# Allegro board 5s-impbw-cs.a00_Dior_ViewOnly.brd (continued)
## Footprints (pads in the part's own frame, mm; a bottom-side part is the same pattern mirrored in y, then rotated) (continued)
MX_BTOB_60P_20_F_PANA
  rect 0.762x2.007 smd: 1(-7.5,-2.2) 30(7.5,-2.2) 31(-7.5,2.2) 60(7.5,2.2)
  rect 0.254x2.007 smd: 2(-6.75,-2.2) 3(-6.25,-2.2) 4(-5.75,-2.2) 5(-5.25,-2.2) 6(-4.75,-2.2) 7(-4.25,-2.2) 8(-3.75,-2.2) 9(-3.25,-2.2) 10(-2.75,-2.2) 11(-2.25,-2.2) 12(-1.75,-2.2) 13(-1.25,-2.2) 14(-0.75,-2.2) 15(-0.25,-2.2) 16(0.25,-2.2) 17(0.75,-2.2) 18(1.25,-2.2) 19(1.75,-2.2) 20(2.25,-2.2) 21(2.75,-2.2) 22(3.25,-2.2) 23(3.75,-2.2) 24(4.25,-2.2) 25(4.75,-2.2) 26(5.25,-2.2) 27(5.75,-2.2) 28(6.25,-2.2) 29(6.75,-2.2) 32(-6.75,2.2) 33(-6.25,2.2) 34(-5.75,2.2) 35(-5.25,2.2) 36(-4.75,2.2) 37(-4.25,2.2) 38(-3.75,2.2) 39(-3.25,2.2) 40(-2.75,2.2) 41(-2.25,2.2) 42(-1.75,2.2) 43(-1.25,2.2) 44(-0.75,2.2) 45(-0.25,2.2) 46(0.25,2.2) 47(0.75,2.2) 48(1.25,2.2) 49(1.75,2.2) 50(2.25,2.2) 51(2.75,2.2) 52(3.25,2.2) 53(3.75,2.2) 54(4.25,2.2) 55(4.75,2.2) 56(5.25,2.2) 57(5.75,2.2) 58(6.25,2.2) 59(6.75,2.2)
MX_C0402
  rect 0.635x0.635 smd: 1(-0.445,0) 2(0.445,0)
MX_C0402_SMALL
  rect 0.457x0.508 smd: 1(0.419,0) 2(-0.419,0)
MX_C0603
  rect 0.889x0.813 smd: 1(-0.635,0) 2(0.635,0)
MX_C0603_SMALL
  rect 0.559x0.889 smd: 1(-0.67,0) 2(0.67,0)
MX_C0805
  rect 1.27x1.27 smd: 1(1.041,0) 2(-1.041,0)
MX_C0805_SMALL
  rect 0.813x1.397 smd: 1(0.9,0) 2(-0.9,0)
MX_C3528
  rect 1.905x2.21 smd: 1(1.816,0) 2(-1.816,0)
MX_C7343D_H75
  rect 2.032x2.616 smd: 1(3.265,0) 2(-3.265,0)
MX_C7343D_H79
  rect 2.032x2.616 smd: 1(3.265,0) 2(-3.265,0)
MX_CHOKE_4P_79X47_FUKUI
  rect 0.889x0.356 smd: 1(-0.85,-0.425) 2(0.85,-0.425) 3(0.85,0.425) 4(-0.85,0.425)
MX_DDR3_DIMM_204P_24_4HL_DA
  round 1.6 hole 1.6 unplated: (-33.4,0)
  round 1.092 hole 1.092 unplated: (33.4,0)
  rect 0.356x2.007 smd: 1(-31.65,-4.1) 2(-31.35,4.1) 3(-31.05,-4.1) 4(-30.75,4.1) 5(-30.45,-4.1) 6(-30.15,4.1) 7(-29.85,-4.1) 8(-29.55,4.1) 9(-29.25,-4.1) 10(-28.95,4.1) 11(-28.65,-4.1) 12(-28.35,4.1) 13(-28.05,-4.1) 14(-27.75,4.1) 15(-27.45,-4.1) 16(-27.15,4.1) 17(-26.85,-4.1) 18(-26.55,4.1) 19(-26.25,-4.1) 20(-25.95,4.1) 21(-25.65,-4.1) 22(-25.35,4.1) 23(-25.05,-4.1) 24(-24.75,4.1) 25(-24.45,-4.1) 26(-24.15,4.1) 27(-23.85,-4.1) 28(-23.55,4.1) 29(-23.25,-4.1) 30(-22.95,4.1) 31(-22.65,-4.1) 32(-22.35,4.1) 33(-22.05,-4.1) 34(-21.75,4.1) 35(-21.45,-4.1) 36(-21.15,4.1) 37(-20.85,-4.1) 38(-20.55,4.1) 39(-20.25,-4.1) 40(-19.95,4.1) 41(-19.65,-4.1) 42(-19.35,4.1) 43(-19.05,-4.1) 44(-18.75,4.1) 45(-18.45,-4.1) 46(-18.15,4.1) 47(-17.85,-4.1) 48(-17.55,4.1) 49(-17.25,-4.1) 50(-16.95,4.1) 51(-16.65,-4.1) 52(-16.35,4.1) 53(-16.05,-4.1) 54(-15.75,4.1) 55(-15.45,-4.1) 56(-15.15,4.1) 57(-14.85,-4.1) 58(-14.55,4.1) 59(-14.25,-4.1) 60(-13.95,4.1) 61(-13.65,-4.1) 62(-13.35,4.1) 63(-13.05,-4.1) 64(-12.75,4.1) 65(-12.45,-4.1) 66(-12.15,4.1) 67(-11.85,-4.1) 68(-11.55,4.1) 69(-11.25,-4.1) 70(-10.95,4.1) 71(-10.65,-4.1) 72(-10.35,4.1) 73(-7.65,-4.1) 74(-7.35,4.1) 75(-7.05,-4.1) 76(-6.75,4.1) 77(-6.45,-4.1) 78(-6.15,4.1) 79(-5.85,-4.1) 80(-5.55,4.1) 81(-5.25,-4.1) 82(-4.95,4.1) 83(-4.65,-4.1) 84(-4.35,4.1) 85(-4.05,-4.1) 86(-3.75,4.1) 87(-3.45,-4.1) 88(-3.15,4.1) 89(-2.85,-4.1) 90(-2.55,4.1) 91(-2.25,-4.1) 92(-1.95,4.1) 93(-1.65,-4.1) 94(-1.35,4.1) 95(-1.05,-4.1) 96(-0.75,4.1) 97(-0.45,-4.1) 98(-0.15,4.1) 99(0.15,-4.1) 100(0.45,4.1) 101(0.75,-4.1) 102(1.05,4.1) 103(1.35,-4.1) 104(1.65,4.1) 105(1.95,-4.1) 106(2.25,4.1) 107(2.55,-4.1) 108(2.85,4.1) 109(3.15,-4.1) 110(3.45,4.1) 111(3.75,-4.1) 112(4.05,4.1) 113(4.35,-4.1) 114(4.65,4.1) 115(4.95,-4.1) 116(5.25,4.1) 117(5.55,-4.1) 118(5.85,4.1) 119(6.15,-4.1) 120(6.45,4.1) 121(6.75,-4.1) 122(7.05,4.1) 123(7.35,-4.1) 124(7.65,4.1) 125(7.95,-4.1) 126(8.25,4.1) 127(8.55,-4.1) 128(8.85,4.1) 129(9.15,-4.1) 130(9.45,4.1) 131(9.75,-4.1) 132(10.05,4.1) 133(10.35,-4.1) 134(10.65,4.1) 135(10.95,-4.1) 136(11.25,4.1) 137(11.55,-4.1) 138(11.85,4.1) 139(12.15,-4.1) 140(12.45,4.1) 141(12.75,-4.1) 142(13.05,4.1) 143(13.35,-4.1) 144(13.65,4.1) 145(13.95,-4.1) 146(14.25,4.1) 147(14.55,-4.1) 148(14.85,4.1) 149(15.15,-4.1) 150(15.45,4.1) 151(15.75,-4.1) 152(16.05,4.1) 153(16.35,-4.1) 154(16.65,4.1) 155(16.95,-4.1) 156(17.25,4.1) 157(17.55,-4.1) 158(17.85,4.1) 159(18.15,-4.1) 160(18.45,4.1) 161(18.75,-4.1) 162(19.05,4.1) 163(19.35,-4.1) 164(19.65,4.1) 165(19.95,-4.1) 166(20.25,4.1) 167(20.55,-4.1) 168(20.85,4.1) 169(21.15,-4.1) 170(21.45,4.1) 171(21.75,-4.1) 172(22.05,4.1) 173(22.35,-4.1) 174(22.65,4.1) 175(22.95,-4.1) 176(23.25,4.1) 177(23.55,-4.1) 178(23.85,4.1) 179(24.15,-4.1) 180(24.45,4.1) 181(24.75,-4.1) 182(25.05,4.1) 183(25.35,-4.1) 184(25.65,4.1) 185(25.95,-4.1) 186(26.25,4.1) 187(26.55,-4.1) 188(26.85,4.1) 189(27.15,-4.1) 190(27.45,4.1) 191(27.75,-4.1) 192(28.05,4.1) 193(28.35,-4.1) 194(28.65,4.1) 195(28.95,-4.1) 196(29.25,4.1) 197(29.55,-4.1) 198(29.85,4.1) 199(30.15,-4.1) 200(30.45,4.1) 201(30.75,-4.1) 202(31.05,4.1) 203(31.35,-4.1) 204(31.65,4.1)
  rect 4.496x4.597 smd: 207(-32.55,12) 208(32.55,12)
MX_DFN_6P_26_79X79_2PAD_IR
  rect 0.381x0.457 smd: 1(-0.65,-0.925) 2(0,-0.925) 3(0.65,-0.925) 4(0.65,0.925) 5(0,0.925) 6(-0.65,0.925)
  rect 1.041x0.965 smd: 7(-0.28,0.002)
  rect 0.229x0.787 smd: 8(0.735,0.002)
MX_ESD_2P_33_39X24_AMA
  rect 0.559x0.61 smd: 1(0.425,0) 2(-0.425,0)
MX_FPC_1X12P_20_2H
  rect 0.292x1.092 smd: 1(-2.75,1.95) 2(-2.25,1.95) 3(-1.75,1.95) 4(-1.25,1.95) 5(-0.75,1.95) 6(-0.25,1.95) 7(0.25,1.95) 8(0.75,1.95) 9(1.25,1.95) 10(1.75,1.95) 11(2.25,1.95) 12(2.75,1.95)
  custom 0.6x0.6 smd: 13(-4.85,0) 14(4.85,0)
MX_FPC_7P_20_2HOLD_RA_ENT_T
  rect 0.292x0.991 smd: 1(-1.5,1.6) 2(-1,1.6) 3(-0.5,1.6) 4(0,1.6) 5(0.5,1.6) 6(1,1.6) 7(1.5,1.6)
  rect 1.499x2.591 smd: 8(-3.85,0) 9(3.85,0)
MX_FPC_10P_20_2H_RA_AC_H79
  rect 0.292x1.092 smd: 1(-2.25,1.95) 2(-1.75,1.95) 3(-1.25,1.95) 4(-0.75,1.95) 5(-0.25,1.95) 6(0.25,1.95) 7(0.75,1.95) 8(1.25,1.95) 9(1.75,1.95) 10(2.25,1.95)
  custom 0.6x0.6 smd: 11(-4.35,0) 12(4.35,0)
MX_FPC_18P_20_2HD_RA_ACE_B
  rect 0.292x1.194 smd: 1(-4.25,3.2) 2(-3.75,3.2) 3(-3.25,3.2) 4(-2.75,3.2) 5(-2.25,3.2) 6(-1.75,3.2) 7(-1.25,3.2) 8(-0.75,3.2) 9(-0.25,3.2) 10(0.25,3.2) 11(0.75,3.2) 12(1.25,3.2) 13(1.75,3.2) 14(2.25,3.2) 15(2.75,3.2) 16(3.25,3.2) 17(3.75,3.2) 18(4.25,3.2)
  rect 2.007x1.803 smd: 19(-7.15,0) 20(7.15,0)
MX_FPC_26P_20_4HD_RA_PANASO
  rect 0.292x0.787 smd: 1(-6.25,2.5) 2(-5.75,2.5) 3(-5.25,2.5) 4(-4.75,2.5) 5(-4.25,2.5) 6(-3.75,2.5) 7(-3.25,2.5) 8(-2.75,2.5) 9(-2.25,2.5) 10(-1.75,2.5) 11(-1.25,2.5) 12(-0.75,2.5) 13(-0.25,2.5) 14(0.25,2.5) 15(0.75,2.5) 16(1.25,2.5) 17(1.75,2.5) 18(2.25,2.5) 19(2.75,2.5) 20(3.25,2.5) 21(3.75,2.5) 22(4.25,2.5) 23(4.75,2.5) 24(5.25,2.5) 25(5.75,2.5) 26(6.25,2.5) 27(-6.75,2.5) 28(6.75,2.5)
  rect 0.406x0.787 smd: 29(-7.75,0) 30(7.75,0)
MX_FPC_CON_5P_39_2HOLD_RA
  rect 0.61x1.092 smd: 1(-2,1.95) 2(-1,1.95) 3(0,1.95) 4(1,1.95) 5(2,1.95)
  custom 0.6x0.6 smd: 6(-4.6,0) 7(4.6,0)
MX_FUSE_2P_125X60_H23
  rect 1.143x2.032 smd: 1(-1.33,0) 2(1.33,0)
MX_HD_2X5P_50_K1K3K5K6K79_J
  round 1.067 hole 0.762: 2(-2.54,0) 4(-1.27,0) 8(1.27,0) 10(2.54,0)
MX_HOLE_C59D59N
  round 1.499 hole 1.499 unplated: (0,0)
MX_HOLE_C118D118N
  round 2.997 hole 2.997 unplated: (0,0)
MX_INDUCTOR_2P_205X185
  rect 1.905x2.489 smd: 1(-1.95,0) 2(1.95,0)
MX_INDUCTOR_2P_274X260
  rect 2.362x3.505 smd: 1(-3.025,0) 2(3.025,0)
MX_INDUCTOR_2P_278X260_H118
  rect 2.362x3.505 smd: 1(-3.025,0) 2(3.025,0)
MX_INDUCTOR_2P_287X260
  rect 2.845x2.997 smd: 1(-3.025,0) 2(3.025,0)
MX_L0402_SMALL
  rect 0.457x0.508 smd: 1(-0.419,0) 2(0.419,0)
MX_L0603
  rect 0.889x0.813 smd: 1(-0.635,0) 2(0.635,0)
MX_L0603_SMALL
  rect 0.559x0.889 smd: 1(-0.67,0) 2(0.67,0)
MX_L0805_H41
  rect 1.27x1.27 smd: 1(-1.041,0) 2(1.041,0)
MX_L0805_H43
  rect 1.27x1.27 smd: 1(-1.041,0) 2(1.041,0)
MX_L1206_H51
  rect 1.346x1.6 smd: 1(-1.672,0) 2(1.672,0)
MX_LED_2P_63X31_H16
  rect 0.787x0.787 smd: 1(0.75,0) 2(-0.75,0)
MX_LGA_16P_20_118X118_ST
  rect 0.254x0.356 smd: 1(-1,-1.225) 2(-0.5,-1.225) 3(0,-1.225) 4(0.5,-1.225) 5(1,-1.225) 9(1,1.225) 10(0.5,1.225) 11(0,1.225) 12(-0.5,1.225) 13(-1,1.225)
  rect 0.356x0.254 smd: 6(1.225,-0.5) 7(1.225,0) 8(1.225,0.5) 14(-1.225,0.5) 15(-1.225,0) 16(-1.225,-0.5)
MX_LGA_16P_20_S118_H47
  rect 0.279x0.559 smd: 1(-1,-1.275) 2(-0.5,-1.275) 3(0,-1.275) 4(0.5,-1.275) 5(1,-1.275) 9(1,1.275) 10(0.5,1.275) 11(0,1.275) 12(-0.5,1.275) 13(-1,1.275)
  rect 0.559x0.279 smd: 6(1.275,-0.5) 7(1.275,0) 8(1.275,0.5) 14(-1.275,0.5) 15(-1.275,0) 16(-1.275,-0.5)
MX_LGA_16P_26_157X157_H39
  rect 0.406x0.508 smd: 1(-0.975,-1.7) 2(-0.325,-1.7) 3(0.325,-1.7) 4(0.975,-1.7) 9(0.975,1.7) 10(0.325,1.7) 11(-0.325,1.7) 12(-0.975,1.7)
  rect 0.508x0.406 smd: 5(1.7,-0.975) 6(1.7,-0.325) 7(1.7,0.325) 8(1.7,0.975) 13(-1.7,0.975) 14(-1.7,0.325) 15(-1.7,-0.325) 16(-1.7,-0.975)
MX_MINI_PCI_67P_20_4H_FXN
  round 1.092 hole 1.092 unplated: (-10,0)
  round 1.6 hole 1.6 unplated: (10,0)
  rect 0.292x1.549 smd: 1(-9.25,5.275) 3(-8.75,5.275) 5(-8.25,5.275) 7(-7.75,5.275) 17(-5.25,5.275) 19(-4.75,5.275) 21(-4.25,5.275) 23(-3.75,5.275) 25(-3.25,5.275) 27(-2.75,5.275) 29(-2.25,5.275) 31(-1.75,5.275) 33(-1.25,5.275) 35(-0.75,5.275) 37(-0.25,5.275) 39(0.25,5.275) 41(0.75,5.275) 43(1.25,5.275) 45(1.75,5.275) 47(2.25,5.275) 49(2.75,5.275) 51(3.25,5.275) 53(3.75,5.275) 55(4.25,5.275) 57(4.75,5.275) 59(5.25,5.275) 61(5.75,5.275) 63(6.25,5.275) 65(6.75,5.275) 67(7.25,5.275) 69(7.75,5.275) 71(8.25,5.275) 73(8.75,5.275) 75(9.25,5.275)
  rect 0.292x1.499 smd: 2(-9,-2.3) 4(-8.5,-2.3) 6(-8,-2.3) 16(-5.5,-2.3) 18(-5,-2.3) 20(-4.5,-2.3) 22(-4,-2.3) 24(-3.5,-2.3) 26(-3,-2.3) 28(-2.5,-2.3) 30(-2,-2.3) 32(-1.5,-2.3) 34(-1,-2.3) 36(-0.5,-2.3) 38(0,-2.3) 40(0.5,-2.3) 42(1,-2.3) 44(1.5,-2.3) 46(2,-2.3) 48(2.5,-2.3) 50(3,-2.3) 52(3.5,-2.3) 54(4,-2.3) 56(4.5,-2.3) 58(5,-2.3) 60(5.5,-2.3) 62(6,-2.3) 64(6.5,-2.3) 66(7,-2.3) 68(7.5,-2.3) 70(8,-2.3) 72(8.5,-2.3) 74(9,-2.3)
  rect 1.194x2.743 smd: 76(-10.35,4.5) 77(10.35,4.5)
MX_MINI_PCI_67P_20_4HD_FOXN
  round 1.092 hole 1.092 unplated: (-10,0)
  round 1.6 hole 1.6 unplated: (10,0)
  rect 0.292x1.549 smd: 1(-9.25,5.275) 3(-8.75,5.275) 5(-8.25,5.275) 7(-7.75,5.275) 9(-7.25,5.275) 11(-6.75,5.275) 21(-4.25,5.275) 23(-3.75,5.275) 25(-3.25,5.275) 27(-2.75,5.275) 29(-2.25,5.275) 31(-1.75,5.275) 33(-1.25,5.275) 35(-0.75,5.275) 37(-0.25,5.275) 39(0.25,5.275) 41(0.75,5.275) 43(1.25,5.275) 45(1.75,5.275) 47(2.25,5.275) 49(2.75,5.275) 51(3.25,5.275) 53(3.75,5.275) 55(4.25,5.275) 57(4.75,5.275) 59(5.25,5.275) 61(5.75,5.275) 63(6.25,5.275) 65(6.75,5.275) 67(7.25,5.275) 69(7.75,5.275) 71(8.25,5.275) 73(8.75,5.275) 75(9.25,5.275)
  rect 0.292x1.499 smd: 2(-9,-2.3) 4(-8.5,-2.3) 6(-8,-2.3) 8(-7.5,-2.3) 10(-7,-2.3) 20(-4.5,-2.3) 22(-4,-2.3) 24(-3.5,-2.3) 26(-3,-2.3) 28(-2.5,-2.3) 30(-2,-2.3) 32(-1.5,-2.3) 34(-1,-2.3) 36(-0.5,-2.3) 38(0,-2.3) 40(0.5,-2.3) 42(1,-2.3) 44(1.5,-2.3) 46(2,-2.3) 48(2.5,-2.3) 50(3,-2.3) 52(3.5,-2.3) 54(4,-2.3) 56(4.5,-2.3) 58(5,-2.3) 60(5.5,-2.3) 62(6,-2.3) 64(6.5,-2.3) 66(7,-2.3) 68(7.5,-2.3) 70(8,-2.3) 72(8.5,-2.3) 74(9,-2.3)
  rect 1.194x2.743 smd: 76(-10.35,4.5) 77(10.35,4.5)
MX_NUT_CT217B118D47_H165
  round 2.997 hole 1.194: 1(0,0)
MX_POLYSWITCH_2P_1206
  rect 1.499x2.057 smd: 1(-1.4,0) 2(1.4,0)
MX_QFN_16P_118X188_MPS
  rect 0.203x1.092 smd: 1(-0.525,-1.25) 2(0.175,-1.25) 8(0.525,1.25) 9(-0.175,1.25)
  rect 0.711x0.197 smd: 3(1.45,-0.8) 4(1.45,-0.4) 5(1.45,0) 6(1.45,0.4) 7(1.45,0.8) 10(-1.45,0.8) 11(-1.45,0.4) 12(-1.45,0) 13(-1.45,-0.4) 14(-1.45,-0.8)
  rect 0.203x0.66 smd: 15(-0.165,0) 16(0.435,0)
MX_QFN_20P_16_S118_PAD_2V
  rect 0.197x0.61 smd: 1(-0.8,-1.35) 2(-0.4,-1.35) 3(0,-1.35) 4(0.4,-1.35) 5(0.8,-1.35) 11(0.8,1.35) 12(0.4,1.35) 13(0,1.35) 14(-0.4,1.35) 15(-0.8,1.35)
  rect 0.61x0.197 smd: 6(1.35,-0.8) 7(1.35,-0.4) 8(1.35,0) 9(1.35,0.4) 10(1.35,0.8) 16(-1.35,0.8) 17(-1.35,0.4) 18(-1.35,0) 19(-1.35,-0.4) 20(-1.35,-0.8)
  rect 1.651x1.651 smd: 21(0,0)
  round 0.61 hole 0.305: 22(-0.521,0.521) 23(0.521,-0.521)
MX_QFN_20P_16_S118_PAD_4V
  rect 0.197x0.61 smd: 1(-0.8,-1.35) 2(-0.4,-1.35) 3(0,-1.35) 4(0.4,-1.35) 5(0.8,-1.35) 11(0.8,1.35) 12(0.4,1.35) 13(0,1.35) 14(-0.4,1.35) 15(-0.8,1.35)
  rect 0.61x0.197 smd: 6(1.35,-0.8) 7(1.35,-0.4) 8(1.35,0) 9(1.35,0.4) 10(1.35,0.8) 16(-1.35,0.8) 17(-1.35,0.4) 18(-1.35,0) 19(-1.35,-0.4) 20(-1.35,-0.8)
  rect 1.651x1.651 smd: 21(0,0)
  round 0.61 hole 0.305: 22(-0.521,0.521) 23(0.521,0.521) 24(-0.521,-0.521) 25(0.521,-0.521)
MX_QFN_20P_20_S138_PAD_4V
  rect 0.279x0.61 smd: 1(-1,-1.6) 2(-0.5,-1.6) 3(0,-1.6) 4(0.5,-1.6) 5(1,-1.6) 11(1,1.6) 12(0.5,1.6) 13(0,1.6) 14(-0.5,1.6) 15(-1,1.6)
  rect 0.61x0.279 smd: 6(1.6,-1) 7(1.6,-0.5) 8(1.6,0) 9(1.6,0.5) 10(1.6,1) 16(-1.6,1) 17(-1.6,0.5) 18(-1.6,0) 19(-1.6,-0.5) 20(-1.6,-1)
  rect 2.159x2.159 smd: 21(0,0)
  round 0.61 hole 0.305: 22(-0.775,0.775) 23(0.775,0.775) 24(-0.775,-0.775) 25(0.775,-0.775)
MX_QFN_20P_20_S157_P83_4V
  rect 0.279x0.762 smd: 1(-1,-1.775) 2(-0.5,-1.775) 3(0,-1.775) 4(0.5,-1.775) 5(1,-1.775) 11(1,1.775) 12(0.5,1.775) 13(0,1.775) 14(-0.5,1.775) 15(-1,1.775)
  rect 0.762x0.279 smd: 6(1.775,-1) 7(1.775,-0.5) 8(1.775,0) 9(1.775,0.5) 10(1.775,1) 16(-1.775,1) 17(-1.775,0.5) 18(-1.775,0) 19(-1.775,-0.5) 20(-1.775,-1)
  rect 2.108x2.108 smd: 21(0,0)
  round 0.61 hole 0.305: 22(-0.5,0.5) 23(0.5,0.5) 24(0.5,-0.5) 25(-0.5,-0.5)
MX_QFN_24P_20_S157_PAD_IN
  rect 0.279x0.61 smd: 1(-1.25,-1.85) 2(-0.75,-1.85) 3(-0.25,-1.85) 4(0.25,-1.85) 5(0.75,-1.85) 6(1.25,-1.85) 13(1.25,1.85) 14(0.75,1.85) 15(0.25,1.85) 16(-0.25,1.85) 17(-0.75,1.85) 18(-1.25,1.85)
  rect 0.61x0.279 smd: 7(1.85,-1.25) 8(1.85,-0.75) 9(1.85,-0.25) 10(1.85,0.25) 11(1.85,0.75) 12(1.85,1.25) 19(-1.85,1.25) 20(-1.85,0.75) 21(-1.85,0.25) 22(-1.85,-0.25) 23(-1.85,-0.75) 24(-1.85,-1.25)
  rect 2.108x2.108 smd: 25(0,0)
MX_QFN_32P_16_S157_P_H39_4V
  rect 0.197x0.508 smd: 1(-1.4,-1.901) 8(1.4,-1.901) 17(1.4,1.901) 24(-1.4,1.901)
  rect 0.197x0.61 smd: 2(-1,-1.85) 3(-0.6,-1.85) 4(-0.2,-1.85) 5(0.2,-1.85) 6(0.6,-1.85) 7(1,-1.85) 18(1,1.85) 19(0.6,1.85) 20(0.2,1.85) 21(-0.2,1.85) 22(-0.6,1.85) 23(-1,1.85)
  rect 0.508x0.197 smd: 9(1.901,-1.4) 16(1.901,1.4) 25(-1.901,1.4) 32(-1.901,-1.4)
  rect 0.61x0.197 smd: 10(1.85,-1) 11(1.85,-0.6) 12(1.85,-0.2) 13(1.85,0.2) 14(1.85,0.6) 15(1.85,1) 26(-1.85,1) 27(-1.85,0.6) 28(-1.85,0.2) 29(-1.85,-0.2) 30(-1.85,-0.6) 31(-1.85,-1)
  rect 2.667x2.667 smd: 33(0,0)
  round 0.61 hole 0.305: 34(-1.029,1.029) 35(1.029,1.029) 36(-1.029,-1.029) 37(1.029,-1.029)
MX_QFN_64P_16_S315_PAD_ANA
  rect 0.197x0.61 smd: 1(-3,-3.85) 2(-2.6,-3.85) 3(-2.2,-3.85) 4(-1.8,-3.85) 5(-1.4,-3.85) 6(-1,-3.85) 7(-0.6,-3.85) 8(-0.2,-3.85) 9(0.2,-3.85) 10(0.6,-3.85) 11(1,-3.85) 12(1.4,-3.85) 13(1.8,-3.85) 14(2.2,-3.85) 15(2.6,-3.85) 16(3,-3.85) 33(3,3.85) 34(2.6,3.85) 35(2.2,3.85) 36(1.8,3.85) 37(1.4,3.85) 38(1,3.85) 39(0.6,3.85) 40(0.2,3.85) 41(-0.2,3.85) 42(-0.6,3.85) 43(-1,3.85) 44(-1.4,3.85) 45(-1.8,3.85) 46(-2.2,3.85) 47(-2.6,3.85) 48(-3,3.85)
  rect 0.61x0.197 smd: 17(3.85,-3) 18(3.85,-2.6) 19(3.85,-2.2) 20(3.85,-1.8) 21(3.85,-1.4) 22(3.85,-1) 23(3.85,-0.6) 24(3.85,-0.2) 25(3.85,0.2) 26(3.85,0.6) 27(3.85,1) 28(3.85,1.4) 29(3.85,1.8) 30(3.85,2.2) 31(3.85,2.6) 32(3.85,3) 49(-3.85,3) 50(-3.85,2.6) 51(-3.85,2.2) 52(-3.85,1.8) 53(-3.85,1.4) 54(-3.85,1) 55(-3.85,0.6) 56(-3.85,0.2) 57(-3.85,-0.2) 58(-3.85,-0.6) 59(-3.85,-1) 60(-3.85,-1.4) 61(-3.85,-1.8) 62(-3.85,-2.2) 63(-3.85,-2.6) 64(-3.85,-3)
  rect 4.242x4.242 smd: 65(0,0)
MX_QFP_48P_20_354X354_H63
  rect 0.279x1.499 smd: 1(-2.75,-4.36) 2(-2.25,-4.36) 3(-1.75,-4.36) 4(-1.25,-4.36) 5(-0.75,-4.36) 6(-0.25,-4.36) 7(0.25,-4.36) 8(0.75,-4.36) 9(1.25,-4.36) 10(1.75,-4.36) 11(2.25,-4.36) 12(2.75,-4.36) 25(2.75,4.36) 26(2.25,4.36) 27(1.75,4.36) 28(1.25,4.36) 29(0.75,4.36) 30(0.25,4.36) 31(-0.25,4.36) 32(-0.75,4.36) 33(-1.25,4.36) 34(-1.75,4.36) 35(-2.25,4.36) 36(-2.75,4.36)
  rect 1.499x0.279 smd: 13(4.36,-2.75) 14(4.36,-2.25) 15(4.36,-1.75) 16(4.36,-1.25) 17(4.36,-0.75) 18(4.36,-0.25) 19(4.36,0.25) 20(4.36,0.75) 21(4.36,1.25) 22(4.36,1.75) 23(4.36,2.25) 24(4.36,2.75) 37(-4.36,2.75) 38(-4.36,2.25) 39(-4.36,1.75) 40(-4.36,1.25) 41(-4.36,0.75) 42(-4.36,0.25) 43(-4.36,-0.25) 44(-4.36,-0.75) 45(-4.36,-1.25) 46(-4.36,-1.75) 47(-4.36,-2.25) 48(-4.36,-2.75)
MX_QFP_128P_16_630X630
  rect 0.191x1.499 smd: 1(-6.2,-7.86) 2(-5.8,-7.86) 3(-5.4,-7.86) 4(-5,-7.86) 5(-4.6,-7.86) 6(-4.2,-7.86) 7(-3.8,-7.86) 8(-3.4,-7.86) 9(-3,-7.86) 10(-2.6,-7.86) 11(-2.2,-7.86) 12(-1.8,-7.86) 13(-1.4,-7.86) 14(-1,-7.86) 15(-0.6,-7.86) 16(-0.2,-7.86) 17(0.2,-7.86) 18(0.6,-7.86) 19(1,-7.86) 20(1.4,-7.86) 21(1.8,-7.86) 22(2.2,-7.86) 23(2.6,-7.86) 24(3,-7.86) 25(3.4,-7.86) 26(3.8,-7.86) 27(4.2,-7.86) 28(4.6,-7.86) 29(5,-7.86) 30(5.4,-7.86) 31(5.8,-7.86) 32(6.2,-7.86) 65(6.2,7.86) 66(5.8,7.86) 67(5.4,7.86) 68(5,7.86) 69(4.6,7.86) 70(4.2,7.86) 71(3.8,7.86) 72(3.4,7.86) 73(3,7.86) 74(2.6,7.86) 75(2.2,7.86) 76(1.8,7.86) 77(1.4,7.86) 78(1,7.86) 79(0.6,7.86) 80(0.2,7.86) 81(-0.2,7.86) 82(-0.6,7.86) 83(-1,7.86) 84(-1.4,7.86) 85(-1.8,7.86) 86(-2.2,7.86) 87(-2.6,7.86) 88(-3,7.86) 89(-3.4,7.86) 90(-3.8,7.86) 91(-4.2,7.86) 92(-4.6,7.86) 93(-5,7.86) 94(-5.4,7.86) 95(-5.8,7.86) 96(-6.2,7.86)
  rect 1.499x0.191 smd: 33(7.86,-6.2) 34(7.86,-5.8) 35(7.86,-5.4) 36(7.86,-5) 37(7.86,-4.6) 38(7.86,-4.2) 39(7.86,-3.8) 40(7.86,-3.4) 41(7.86,-3) 42(7.86,-2.6) 43(7.86,-2.2) 44(7.86,-1.8) 45(7.86,-1.4) 46(7.86,-1) 47(7.86,-0.6) 48(7.86,-0.2) 49(7.86,0.2) 50(7.86,0.6) 51(7.86,1) 52(7.86,1.4) 53(7.86,1.8) 54(7.86,2.2) 55(7.86,2.6) 56(7.86,3) 57(7.86,3.4) 58(7.86,3.8) 59(7.86,4.2) 60(7.86,4.6) 61(7.86,5) 62(7.86,5.4) 63(7.86,5.8) 64(7.86,6.2) 97(-7.86,6.2) 98(-7.86,5.8) 99(-7.86,5.4) 100(-7.86,5) 101(-7.86,4.6) 102(-7.86,4.2) 103(-7.86,3.8) 104(-7.86,3.4) 105(-7.86,3) 106(-7.86,2.6) 107(-7.86,2.2) 108(-7.86,1.8) 109(-7.86,1.4) 110(-7.86,1) 111(-7.86,0.6) 112(-7.86,0.2) 113(-7.86,-0.2) 114(-7.86,-0.6) 115(-7.86,-1) 116(-7.86,-1.4) 117(-7.86,-1.8) 118(-7.86,-2.2) 119(-7.86,-2.6) 120(-7.86,-3) 121(-7.86,-3.4) 122(-7.86,-3.8) 123(-7.86,-4.2) 124(-7.86,-4.6) 125(-7.86,-5) 126(-7.86,-5.4) 127(-7.86,-5.8) 128(-7.86,-6.2)
MX_R0402
  rect 0.635x0.635 smd: 1(-0.445,0) 2(0.445,0)
MX_R0402_SHORT
  rect 0.635x0.635 smd: 1(-0.445,0) 2(0.445,0)
MX_R0402_SHORT_SMALL
  rect 0.457x0.508 smd: 1(-0.419,0) 2(0.419,0)
MX_R0402_SMALL
  rect 0.457x0.508 smd: 1(-0.419,0) 2(0.419,0)
MX_R0603
  rect 0.889x0.813 smd: 1(-0.635,0) 2(0.635,0)
MX_R0603_SHORT_SMALL
  rect 0.559x0.889 smd: 1(-0.67,0) 2(0.67,0)
MX_R0603_SMALL
  rect 0.559x0.889 smd: 1(-0.67,0) 2(0.67,0)
MX_R0805
  rect 1.27x1.27 smd: 1(-1.041,0) 2(1.041,0)
MX_R0805_H24_SMALL
  rect 0.813x1.397 smd: 1(-0.9,0) 2(0.9,0)
MX_R0805_H26_SMALL
  rect 0.813x1.397 smd: 1(-0.9,0) 2(0.9,0)
MX_R0805_SHORT_SMALL
  rect 0.813x1.397 smd: 1(-0.9,0) 2(0.9,0)
MX_R0805_SMALL
  rect 0.813x1.397 smd: 1(-0.9,0) 2(0.9,0)
MX_R1206
  rect 1.118x1.6 smd: 1(-1.557,0) 2(1.557,0)
MX_R1508
  rect 0.991x3.759 smd: 1(-1,0) 2(1,0)
MX_S0402_AMAZ
  rect 0.381x0.406 smd: 1(-0.35,0) 2(0.35,0)
MX_SATA_CON_22P_50_4H_RA_P2
  round 1.753 hole 1.753 unplated: (-16.595,0) (16.595,0)
  oval 2.007x3.099 hole 0.991: 25(-18.71,0.75) 26(18.71,0.75)
  round 1.016 hole 0.711: P1(1.905,1.46) P2(0.635,1.46) P3(-0.635,1.46) P4(-1.905,1.46) P5(-3.175,1.46) P6(-4.445,1.46) P7(-5.715,1.46) P8(-6.985,1.46) P9(-8.255,1.46) P10(-9.525,1.46) P11(-10.795,1.46) P12(-12.065,1.46) P13(-13.335,1.46) P14(-14.605,1.46) P15(-15.875,1.46) S1(15.875,1.46) S2(14.605,1.46) S3(13.335,1.46) S4(12.065,1.46) S5(10.795,1.46) S6(9.525,1.46) S7(8.255,1.46)
MX_SC70_C5
  rect 0.94x0.356 smd: 1(1.19,-0.65) 2(1.19,0) 3(1.19,0.65) 4(-1.19,0.65) 5(-1.19,-0.65)
MX_SC_75A_ROHM
  rect 0.508x0.457 smd: 1(-0.5,-0.775) 2(0.5,-0.775) 3(0.5,0.775) 4(-0.5,0.775)
MX_SCONN60_EPG082001
  round 1.194 hole 1.194 unplated: (-10.059,2.666) (10.064,2.666)
  rect 0.279x2.286 smd: 1(-7.25,-3.499) 2(-7.25,3.499) 3(-6.75,-3.499) 4(-6.75,3.499) 5(-6.25,-3.499) 6(-6.25,3.499) 7(-5.75,-3.499) 8(-5.75,3.499) 9(-5.25,-3.499) 10(-5.25,3.499) 11(-4.75,-3.499) 12(-4.75,3.499) 13(-4.25,-3.499) 14(-4.25,3.499) 15(-3.75,-3.499) 16(-3.75,3.499) 17(-3.25,-3.499) 18(-3.25,3.499) 19(-2.75,-3.499) 20(-2.75,3.499) 21(-2.25,-3.499) 22(-2.25,3.499) 23(-1.75,-3.499) 24(-1.75,3.499) 25(-1.25,-3.499) 26(-1.25,3.499) 27(-0.75,-3.499) 28(-0.75,3.499) 29(-0.25,-3.499) 30(-0.25,3.499) 31(0.25,-3.499) 32(0.25,3.499) 33(0.75,-3.499) 34(0.75,3.499) 35(1.25,-3.499) 36(1.25,3.499) 37(1.75,-3.499) 38(1.75,3.499) 39(2.25,-3.499) 40(2.25,3.499) 41(2.75,-3.499) 42(2.75,3.499) 43(3.25,-3.499) 44(3.25,3.499) 45(3.75,-3.499) 46(3.75,3.499) 47(4.25,-3.499) 48(4.25,3.499) 49(4.75,-3.499) 50(4.75,3.499) 51(5.25,-3.499) 52(5.25,3.499) 53(5.75,-3.499) 54(5.75,3.499) 55(6.25,-3.499) 56(6.25,3.499) 57(6.75,-3.499) 58(6.75,3.499) 59(7.25,-3.499) 60(7.25,3.499)
MX_SHORTPIN_RECTANGLE_LF3
  rect 0.737x0.813 smd: 1(-0.521,0) 2(0.521,0)
MX_SMT_NUT_CT197B63D47_H102
  round 1.6 hole 1.194: 1(0,0)
MX_SMT_NUT_CT217B160D130
  round 4.064 hole 3.302: 1(0,0)
MX_SO_8FL_COLAY
  rect 0.762x1.524 smd: 1(-1.905,-2.848) 2(-0.635,-2.848) 3(0.635,-2.848) 4(1.905,-2.848)
  rect 4.547x4.826 smd: 5(0,1.083)
MX_SOD323_H35
  rect 1.092x0.508 smd: 1(1.3,0) 2(-1.3,0)
MX_SOD323_H37
  rect 1.092x0.508 smd: 1(1.3,0) 2(-1.3,0)
MX_SOIC_8P_26_122X193_H48
  rect 0.356x1.448 smd: 1(-0.975,-2.335) 2(-0.325,-2.335) 3(0.325,-2.335) 4(0.975,-2.335) 5(0.975,2.335) 6(0.325,2.335) 7(-0.325,2.335) 8(-0.975,2.335)
MX_SOIC_8P_50_197X236
  rect 0.61x1.524 smd: 1(-1.905,-2.857) 2(-0.635,-2.857) 3(0.635,-2.857) 4(1.905,-2.857) 5(1.905,2.857) 6(0.635,2.857) 7(-0.635,2.857) 8(-1.905,2.857)
MX_SOIC_8P_50_213X311
  rect 0.635x1.88 smd: 1(-1.905,-3.62) 2(-0.635,-3.62) 3(0.635,-3.62) 4(1.905,-3.62) 5(1.905,3.62) 6(0.635,3.62) 7(-0.635,3.62) 8(-1.905,3.62)
MX_SOIC_14P_26_201X252
  rect 0.356x1.499 smd: 1(-1.95,-3.06) 2(-1.3,-3.06) 3(-0.65,-3.06) 4(0,-3.06) 5(0.65,-3.06) 6(1.3,-3.06) 7(1.95,-3.06) 8(1.95,3.06) 9(1.3,3.06) 10(0.65,3.06) 11(0,3.06) 12(-0.65,3.06) 13(-1.3,3.06) 14(-1.95,3.06)
MX_SOIC_28P_26_386X252
  rect 0.356x1.499 smd: 1(-4.225,-3.06) 2(-3.575,-3.06) 3(-2.925,-3.06) 4(-2.275,-3.06) 5(-1.625,-3.06) 6(-0.975,-3.06) 7(-0.325,-3.06) 8(0.325,-3.06) 9(0.975,-3.06) 10(1.625,-3.06) 11(2.275,-3.06) 12(2.925,-3.06) 13(3.575,-3.06) 14(4.225,-3.06) 15(4.225,3.06) 16(3.575,3.06) 17(2.925,3.06) 18(2.275,3.06) 19(1.625,3.06) 20(0.975,3.06) 21(0.325,3.06) 22(-0.325,3.06) 23(-0.975,3.06) 24(-1.625,3.06) 25(-2.275,3.06) 26(-2.925,3.06) 27(-3.575,3.06) 28(-4.225,3.06)
MX_SOP_9P_16_177X138_9V
  rect 0.197x0.61 smd: 1(-1.6,-1.6) 2(-1.2,-1.6) 3(-0.8,-1.6) 6(-0.8,1.6) 7(-1.2,1.6) 8(-1.6,1.6)
  custom 0.15x0.15 smd: 4(0.601,-1.6) 5(0.601,1.6)
  rect 4.039x1.956 smd: 9(0,0)
  round 0.61 hole 0.305: 10(-1.62,0.673) 11(0,0.673) 12(1.62,0.673) 13(-1.62,0) 14(0,0) 15(1.62,0) 16(-1.62,-0.673) 17(0,-0.673) 18(1.62,-0.673)
MX_SOT23
  rect 1.27x0.686 smd: 1(1.041,-0.95) 2(1.041,0.95) 3(-1.041,0)
MX_SOT23_2D4_H44
  rect 0.711x1.016 smd: 1(-0.95,-1.301) 2(0.95,-1.301) 3(0,1.301)
MX_SOT23_2D4_H51
  rect 0.711x1.016 smd: 1(-0.95,-1.301) 2(0.95,-1.301) 3(0,1.301)
MX_SOT23_2D4_H55
  rect 0.711x1.016 smd: 1(-0.95,-1.301) 2(0.95,-1.301) 3(0,1.301)
MX_SOT23_H43
  rect 1.27x0.686 smd: 1(1.041,-0.95) 2(1.041,0.95) 3(-1.041,0)
MX_SOT23_S5_H51
  rect 1.118x0.61 smd: 1(1.45,-0.95) 2(1.45,0) 3(1.45,0.95) 4(-1.45,0.95) 5(-1.45,-0.95)
MX_SOT23_S5_H57
  rect 1.118x0.61 smd: 1(1.45,-0.95) 2(1.45,0) 3(1.45,0.95) 4(-1.45,0.95) 5(-1.45,-0.95)
MX_SOT323
  rect 0.914x0.813 smd: 1(0.97,-0.65) 2(0.97,0.65) 3(-0.97,0)
MX_SOT323_S5
  rect 0.356x0.94 smd: 1(-0.65,-1.19) 2(0,-1.19) 3(0.65,-1.19) 4(0.65,1.19) 5(-0.65,1.19)
MX_SOT363
  rect 0.406x0.762 smd: 1(-0.65,-0.95) 2(0,-0.95) 3(0.65,-0.95) 4(0.65,0.95) 5(0,0.95) 6(-0.65,0.95)
MX_SW_5P_315X244_H98
  rect 1.6x1.397 smd: 1(-4.2,2.25) 2(-4.2,-2.25) 3(4.2,2.25) 4(4.2,-2.25) 5(4.2,0)
MX_TPC26B_S4_68
  round 0.66 smd: 1(0,0)
MX_U_DFN3030_8P_26_118X118
  rect 0.381x0.66 smd: 1(0.975,-1.3) 2(0.325,-1.3) 3(-0.325,-1.3) 4(-0.975,-1.3)
  rect 2.591x2.388 smd: 5(0,0.431)
MX_WTOB_2P_49_2H_ACES
  rect 0.787x1.6 smd: 1(0.625,2.9) 2(-0.625,2.9)
  rect 2.108x2.997 smd: 3(3.175,0) 4(-3.175,0)
MX_WTOB_4P_31_2H_RA
  rect 0.508x0.991 smd: 1(1.2,1.95) 2(0.4,1.95) 3(-0.4,1.95) 4(-1.2,1.95)
  rect 1.194x1.702 smd: 5(-2.5,0) 6(2.5,0)
MX_WTOB_4P_49_RA
  rect 0.813x2.108 smd: 1(1.875,1.054) 2(0.625,1.054) 3(-0.625,1.054) 4(-1.875,1.054)
  rect 2.108x2.997 smd: 5(-4.425,-2.1) 6(4.425,-2.1)
MX_WTOB_5P_49_2H_RA_ENTER
  rect 0.787x1.905 smd: 1(2.5,4.875) 2(1.25,4.875) 3(0,4.875) 4(-1.25,4.875) 5(-2.5,4.875)
  rect 1.295x3.353 smd: 6(-5.35,0) 7(5.35,0)
MX_WTOB_5P_59_RA_F_ACES
  rect 0.61x7.01 smd: 1(3,0) 5(-3,0)
  rect 1.092x7.01 smd: 2(1.5,0) 3(0,0) 4(-1.5,0)
MX_WTOB_9P_59_2HD_RA_ACES
  rect 0.66x5.004 smd: 1(6,4.45) 2(4.5,4.45) 3(3,4.45) 4(1.5,4.45) 5(0,4.45) 6(-1.5,4.45) 7(-3,4.45) 8(-4.5,4.45) 9(-6,4.45)
  rect 2.489x2.997 smd: 10(-8.5,0) 11(8.5,0)
MX_WTOB_11P_31_2HOLD_ACES
  rect 0.508x1.651 smd: 1(4,2.275) 2(3.2,2.275) 3(2.4,2.275) 4(1.6,2.275) 5(0.8,2.275) 6(0,2.275) 7(-0.8,2.275) 8(-1.6,2.275) 9(-2.4,2.275) 10(-3.2,2.275) 11(-4,2.275)
  rect 1.194x1.702 smd: 12(5.3,0) 13(-5.3,0)
MX_WTOB_CON_40P_20_4H_SC
  rect 0.254x0.889 smd: 1(9.75,2.82) 2(9.25,2.82) 3(8.75,2.82) 4(8.25,2.82) 5(7.75,2.82) 6(7.25,2.82) 7(6.75,2.82) 8(6.25,2.82) 9(5.75,2.82) 10(5.25,2.82) 11(4.75,2.82) 12(4.25,2.82) 13(3.75,2.82) 14(3.25,2.82) 15(2.75,2.82) 16(2.25,2.82) 17(1.75,2.82) 18(1.25,2.82) 19(0.75,2.82) 20(0.25,2.82) 21(-0.25,2.82) 22(-0.75,2.82) 23(-1.25,2.82) 24(-1.75,2.82) 25(-2.25,2.82) 26(-2.75,2.82) 27(-3.25,2.82) 28(-3.75,2.82) 29(-4.25,2.82) 30(-4.75,2.82) 31(-5.25,2.82) 32(-5.75,2.82) 33(-6.25,2.82) 34(-6.75,2.82) 35(-7.25,2.82) 36(-7.75,2.82) 37(-8.25,2.82) 38(-8.75,2.82) 39(-9.25,2.82) 40(-9.75,2.82)
  rect 0.559x0.889 smd: 41(10.65,2.82) 42(-10.65,2.82)
  rect 1.397x1.905 smd: 43(12.85,0) 44(-12.85,0)
MX_XTAL_2P_126X59_CITIZEN
  rect 1.092x1.905 smd: 1(-1.25,0) 2(1.25,0)
MX_XTAL_4P_126X98_HELE
  rect 1.397x1.194 smd: 1(-1.1,-0.85) 2(1.1,-0.85) 3(1.1,0.85) 4(-1.1,0.85)
MX_XTAL_4P_272X55
  rect 1.194x0.61 smd: 1(-3.15,-0.45) 2(3.15,-0.45) 3(3.15,0.45) 4(-3.15,0.45)
NB_H_2D_D87N_D83_M2_P2_V4
  round 2.21 hole 2.21 unplated: (0,0)
  round 2.616 hole 2.108: 1(0,-3.5)
  round 0.61 hole 0.305: 3(0,1.759) 4(1.759,0) 5(0,-1.759) 6(-1.759,0)
NB_H_2D_D87N_DO83X102_P2_V4
  round 2.21 hole 2.21 unplated: (0,0)
  oval 2.616x3.099 hole 2.108: 1(-4,0)
  round 0.61 hole 0.305: 3(0,1.992) 4(1.992,0) 5(0,-1.992) 6(-1.992,0)
NB_H_2D_DO102X83_D87N_P2_V4
  round 2.21 hole 2.21 unplated: (0,0)
  oval 3.099x2.616 hole 2.108: 1(0,4)
  round 0.61 hole 0.305: 3(0,2.133) 4(2.133,0) 5(0,-2.133) 6(-2.133,0)
NB_H_S276D87N_M2_P2_V4
  round 2.21 hole 2.21 unplated: (0,0)
  round 0.61 hole 0.305: 2(-2.756,-0.751) 3(2.432,0) 4(0,-2.432) 5(-2.432,0)
NB_H_S276D87N_M2_P2_V4#2
  round 2.21 hole 2.21 unplated: (0,0)
  round 0.61 hole 0.305: 2(0,2.432) 3(2.432,0) 4(0,-2.432) 5(-2.432,0)
TPC85B_68
  round 2.159 smd: 1(0,0)
TV_RTC_SHORT_6X20
  rect 0.152x0.508 smd: 1(-0.152,0) 2(0.152,0)
unnamed
  round 4.064 hole 4.064 unplated: (0,0)
unnamed#3
  round 1.016 smd: 1(0,0)

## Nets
+1.05VM_VCCASW4: PR40.2 U1.AG14
+1.05VM_VCCASW5: PR41.2 U1.AG13
+1.05VS_AIDLE: PC220.1 PR35.1 U1.N8 U1.P9
+1.05VS_APLLOPI: PC16.1 PCE1.1 PL3.2 U1.AA21 U1.W21
+1.05VS_AUSB3PLL: PC7.1 PC11.1 PC12.1 PL1.2 SR10.1 U1.B18 U1.B27
+1.05VS_HSIO: PL1.1 PL2.1 PQ1.2 PR32.1 PR49.1 SR7.2 U1.A12
+1.05VS_PWRGD: GU1.1 GU1.4 GU1.10 GU1.13
+1.05VS_PWRGD_S: GR7.2 HR27.1 HR47.2 HU4.4
+1.05VS_PWRGD_S_R: HR27.2 U1.B59
+1.05VS_PWRGD_XDP: GR7.1 XDP1.39
+1.05VS_VCC_AXCK_DCB: PC34.1 PCE2.1 PL4.2 U1.J18 U1.K19
+1.05VS_VCCACLKPLL: PC35.1 PCE3.1 PL5.2 U1.A20
+1.05VS_VCCHSIO: PC3.1 PC4.1 PR32.2 U1.K9 U1.L10 U1.M9
+1.05VSUS_AOSCSUS: PC38.1 U1.AB8
+3VA: C82.1 CR1.1 D1.1 PC187.1 PC201.1 PC218.1 PC224.1 PCE6.1 PJP13.2 PL16.2 PQ27.3 PQ33.3 PQ36.3 PR12.1 PR29.1 PR30.1 PR36.1 PR44.2 PR80.1 PR81.1 PR82.1 PR83.1 PR144.1 R89.1 R179.1 R180.1 R218.2 R314.1 R320.1 R347.1 SR9.1 SR97.1
+3VA_BST1_D: PC134.1 PR150.2
+3VA_BST_D: PR150.1 PU6.9
+3VA_CS_A: PR152.2 PU6.5
+3VA_EC: C69.1 C70.1 C71.1 C75.1 C76.1 D5.1 D8.1 R174.1 R175.1 R179.2 R190.1 R191.1 R193.1 R194.1 R195.1 R196.1 R199.1 R200.1 R201.1 R202.1 R203.1 R204.1 R206.1 R229.1 R435.1 U10.26 U10.50 U10.92 U10.114 U10.121 U10.127
+3VA_EN_A: PC138.1 PR155.2 PU6.6
+3VA_FB1_A: PC140.1 PC141.1 PJP13.1 PR158.1
+3VA_FB_A: PC140.2 PR158.2 PR159.1 PU6.4
+3VA_HG_D: PR151.1 PU6.10
+3VA_IN: PC131.1 PC132.1 PL15.2 PQ19.1 PQ19.2 PQ19.5 PQ19.6 PQ19.7
+3VA_LG_D: PR156.1 PU6.11
+3VA_PHASE_R: PC134.2 PC135.2 PL16.1 PQ19.4 PQ19.8 PQ20.1 PQ20.2 PQ20.5 PQ20.6 PQ20.7 PR153.2 PR214.1 PU6.8
+3VA_R1_HG_D: PC135.1 PQ19.3 PR151.2 PR153.1
+3VA_R1_LG_D: PC139.1 PQ20.3 PR156.2
+3VA_SN_C: PC199.1 PR214.2
+3VA_SPI: R218.1 R219.1 R220.1 R221.1 U11.8
+3VM_SPI1_WP#: F3R2.2 F3R9.2 F3U1.3
+3VM_VCCPSPI: PC17.1 PR37.2 PR228.2 U1.Y8
+3VS_VCC: PC32.1 PR45.1 U1.V8 U1.W9
+3VSUS_VCCPUSB: PC27.1 PR42.2 U1.AA9 U1.AC9 U1.AE20 U1.AE21
+5V: C115.1 CON7.1 F3R13.1 PC92.1 PC184.1 PQ24.2 PR103.1 PR134.1 PU5.2 R231.1 R276.1 R294.2 R315.1 T34.1
+5V_DUAL: C176.1 CON10.23 CON10.24 CON10.25 CON10.26 CON10.27 CON10.28 CON10.29 CON10.30 CON11.14 PC195.1 PQ30.4 PQ30.8 R274.1 R321.1
+5V_DUAL_G_B: PC196.1 PQ30.3 PR206.2
+5V_G_B: PC200.1 PQ24.1 PR195.2
+5V_LCD: C138.1 C139.1 C140.1 C141.1 C142.1 C143.1 P2.1 P2.2 Q21.2 R318.1
+5V_SATA: C91.1 C92.1 C93.1 CON3.P7 CON3.P8 CON3.P9 R231.2 R232.1
+5VA: C431.1 CON10.22 CON11.16 D15.2 D18.2 PC117.1 PR67.1 PR68.1 PU6.13 R310.2 R340.1 R345.1
+5VA_FB1_A: PC127.1 PC128.1 PJP12.1 PR147.1
+5VSB: C432.1 CON10.21 PC182.1 PC194.1 PC213.1 PCE5.1 PD6.1 PJP11.2 PJP12.2 PL14.2 PQ24.3 PQ30.1 PQ30.2 PQ30.5 PQ30.6 PQ30.7 PR52.1 PR164.1
+5VSB_BST1_D: PC116.1 PR139.2
+5VSB_BST_D: PR139.1 PU6.17
+5VSB_CS_A: PR149.2 PU6.1
+5VSB_EN_A: PC136.1 PR154.2 PU6.20
+5VSB_FB_A: PC127.2 PR147.2 PR148.1 PU6.2
+5VSB_HG_D: PR140.1 PU6.16
+5VSB_IN: PC113.1 PC114.1 PL13.2 PQ17.1 PQ17.2 PQ17.5 PQ17.6 PQ17.7 PR138.1
+5VSB_PHASE_R: PC116.2 PC118.2 PL14.1 PQ17.4 PQ17.8 PQ18.1 PQ18.2 PQ18.5 PQ18.6 PQ18.7 PR141.2 PR142.1 PU6.18
+5VSB_R1_HG_D: PC118.1 PQ17.3 PR140.2 PR141.1
+5VSB_R1_LG_D: PC121.1 PQ18.3 PR143.2
+5VSB_SN_C: PC122.1 PR142.2
+5VSB_VIN_C: PD8.2 PQ34.3 R437.1
+5VSB_VIN_C_R: PC115.1 PR138.2 PU6.12 R437.2
+5VSB_VO1_A: PJP11.1 PR146.2
+5VSB_VO_A: PC124.1 PR146.1 PU6.14
+5VSBLG_D: PR143.1 PU6.15
+12V_+19V: C177.1 C433.1 CON10.4 CON10.5 PC186.1 PQ26.3 Q40.2 Q40.5 R432.1 SQ1.2 SQ1.5 SQ2.2 SQ2.5
+15VSB: PC129.1 PD7.2 PR203.1 PR209.1 PR236.1
+15VSB_VCLK: PC123.2 PC126.1 PU6.19
+15VSB_VCLK1: PC123.1 PD6.3
+15VSB_VCLK2: PC125.1 PD6.2 PD7.1
+15VSB_VCLK3: PC126.2 PD7.3
+19V_B: PC190.1 PQ28.1 PR200.2
+19V_BL_F: C134.1 C135.1 C136.1 C137.1 P2.37 P2.38 P2.39 P2.40 PF1.2 R295.2
+19V_GATE: PC185.2 PQ26.1 PR196.2 PR197.2 PR199.1
+19V_GATE1: PQ25.2 PQ28.3 PR199.2
+DVDD: P2.5 R284.1
+VCC_RTC: C48.1 D1.3 PC8.1 PC9.1 PC10.1 PR2.1 R73.1 R74.1 R75.1 R77.1 U1.AG10 U10.3
+VCCDSW: PC31.1 PR44.1 U1.AH10
+VCCIO_OUT: HR21.1 HR33.2 PC73.1 PR98.1 PR99.1 PR100.1
+VCCIO_OUT_R: HC3.1 HR21.2 U1.A59
+VCCIO_OUT_XDP: GC1.1 HR34.2 XDP1.43 XDP1.44
+VCCIOA_OUT: HR16.1 U1.E20
+VCCPRTCSUS: PC6.1 PR33.2 PR36.2 U1.AH11
+VCCRTCEXT: PC18.1 U1.AE7
+VCCST: GR1.1 GR24.1 GR25.1 HC5.1 HC6.1 HR2.1 HR22.1 HR23.1 HR32.2 HR47.1 U1.AC22 U1.AE22 U1.AE23
+VDD_BATA_PACK: C157.1 C158.1 CON8.1 CON8.2 PC58.2 PC67.1 PC68.1 PD3.1 PD8.4 PJP5.2 PQ14.4 PQ14.8 PR92.2 T39.1 T40.1 T41.1 T42.1
AGND_EC: C73.2 C74.2 C83.2 C84.2 C87.2 PRT1.2 PRT2.2 PRT3.2 SP1.1 U10.75
GND: AC1.2 AC2.2 AC3.2 AC4.2 C1.2 C2.2 C3.2 C4.2 C5.2 C6.2 C7.2 C8.2 C9.2 C10.2 C11.2 C12.2 C13.2 C14.2 C15.2 C16.2 C17.2 C18.2 C19.2 C20.2 C21.2 C22.2 C23.2 C24.2 C25.2 C26.2 C27.2 C28.2 C29.2 C30.2 C31.2 C32.2 C33.2 C34.2 C35.2 C36.2 C37.2 C38.2 C39.2 C40.2 C41.2 C48.2 C49.2 C50.2 C51.2 C52.2 C53.2 C54.2 C55.2 C56.2 C57.2 C58.2 C59.2 C60.2 C67.2 C68.2 C69.2 C70.2 C71.2 C72.2 C75.2 C76.2 C77.2 C78.2 C79.2 C80.2 C81.2 C82.2 C85.1 C88.2 C91.2 C92.2 C93.2 C94.2 C95.2 C96.2 C97.2 C98.2 C100.2 C101.2 C102.2 C103.2 C111.2 C112.2 C113.2 C114.2 C115.2 C116.2 C125.2 C126.2 C127.1 C128.2 C129.2 C130.2 C131.2 C132.2 C133.2 C134.2 C135.2 C136.2 C137.2 C138.2 C139.2 C140.2 C141.2 C142.2 C143.2 C144.2 C145.2 C146.2 C147.2 C148.2 C149.2 C150.1 C151.2 C152.2 C153.2 C154.2 C155.2 C156.2 C157.2 C158.2 C159.2 C160.2 C161.2 C162.2 C163.2 C164.2 C165.2 C171.2 C172.2 C173.2 C176.2 C177.2 C178.2 C179.2 C180.2 C181.2 C182.2 C183.2 C184.2 C185.2 C186.2 C187.2 C190.2 C191.2 C192.2 C193.2 C194.2 C195.2 C198.2 C199.2 C200.2 C201.2 C430.2 C431.2 C432.2 C433.2 C1174.2 C1175.2 C1176.2 C1177.2 C1178.2 C1179.2 C1180.2 C1181.2 C1182.2 C1183.2 C1184.2 C1185.2 C1186.2 C1187.2 C1188.2 C1189.2 C1190.2 C1191.2 C1192.2 C1193.2 C1194.2 C1195.2 C9200.2 C9206.2 C9207.2 C9209.2 C9210.2 C9211.2 C9212.2 C9213.2 C9214.2 C9215.2 C9220.2 CA10.2 CA11.2 CA12.2 CA13.2 CB1.2 CB2.2 CB3.2 CB4.2 CB5.2 CB6.2 CB7.2 CE1.2 CKC1.2 CKC2.2 CKC3.2 CKC4.2 CKC5.2 CKC6.2 CKC7.2 CKRN1.2 CKRN1.4 CKRN2.2 CKRN2.4 CKX1.2 CKX1.4 CN1.2 CON1.1 CON2.27 CON2.28 CON2.29 CON2.30 CON3.25 CON3.26 CON3.P4 CON3.P5 CON3.P6 CON3.P10 CON3.P12 CON3.S1 CON3.S4 CON3.S7 CON4.2 CON4.4 CON4.5 CON4.6 CON5.9 CON5.11 CON5.13 CON5.14 CON6.1 CON6.7 CON7.3 CON7.5 CON7.6 CON8.8 CON8.9 CON9.1 CON9.8 CON9.9 CON10.39 CON10.42 CON10.45 CON10.48 CON10.51 CON10.54 CON10.57 CON10.60 CON11.13 CON11.19 CON11.20 CONSATA.3 CONSATA.27 CONSATA.33 CONSATA.39 CONSATA.45 CONSATA.51 CONSATA.57 CONSATA.71 CONSATA.73 CONSATA.76 CONSATA.77 CONWIFI.1 CONWIFI.7 CONWIFI.18 CONWIFI.23 CONWIFI.24 CONWIFI.29 CONWIFI.30 CONWIFI.33 CONWIFI.36 CONWIFI.39 CONWIFI.45 CONWIFI.51 CONWIFI.57 CONWIFI.63 CONWIFI.69 CONWIFI.75 CONWIFI.76 CONWIFI.77 CR5.2 CR6.2 CR8.2 D3C5.2 D3C7.2 D3C8.2 D3CE2.2 D3CE3.2 D3CE4.2 D3CE5.2 D3CE6.2 D3CE7.2 D3CE8.2 D3CE9.2 D3CE20.2 D3CE21.2 D3CE22.2 D3CE23.2 D3CE24.2 D3CE25.2 D3CE26.2 D3CE27.2 D3CE28.2 D3CE36.2 D3CE37.2 D3CE38.2 D3CE39.2 D3CE40.2 D3CE41.2 D5.2 D9.1 D10.2 D11.2 D12.2 D15.1 D16.2 D17.1 D18.1 D19.1 D20.2 D21.2 D22.2 DIMM1.2 DIMM1.3 DIMM1.8 DIMM1.9 DIMM1.11 DIMM1.13 DIMM1.14 DIMM1.19 DIMM1.20 DIMM1.25 DIMM1.26 DIMM1.28 DIMM1.31 DIMM1.32 DIMM1.37 DIMM1.38 DIMM1.43 DIMM1.44 DIMM1.46 DIMM1.48 DIMM1.49 DIMM1.54 DIMM1.55 DIMM1.60 DIMM1.61 DIMM1.63 DIMM1.65 DIMM1.66 DIMM1.71 DIMM1.72 DIMM1.127 DIMM1.128 DIMM1.133 DIMM1.134 DIMM1.136 DIMM1.138 DIMM1.139 DIMM1.144 DIMM1.145 DIMM1.150 DIMM1.151 DIMM1.153 DIMM1.155 DIMM1.156 DIMM1.161 DIMM1.162 DIMM1.167 DIMM1.168 DIMM1.170 DIMM1.172 DIMM1.173 DIMM1.178 DIMM1.179 DIMM1.184 DIMM1.185 DIMM1.187 DIMM1.189 DIMM1.190 DIMM1.195 DIMM1.196 DIMM1.197 DIMM1.207 DIMM1.208 E2.4 E2.8 F3CB4.2 F3J1.3 F3J1.8 F3J1.11 F3J1.12 F3U1.4 GC1.2 GC2.2 GC3.2 GC4.2 GR2.2 GR3.2 GR26.2 GR35.2 GR36.2 GR37.2 GR38.2 GU1.7 GU2.3 H1.1 H2.1 H3.1 H4.1 H9.1 H11.1 H6505.1 H6505.3 H6505.4 H6505.5 H6505.6 H6506.1 H6506.3 H6506.4 H6506.5 H6506.6 H6507.2 H6507.3 H6507.4 H6507.5 H6508.2 H6508.3 H6508.4 H6508.5 H6509.1 H6509.3 H6509.4 H6509.5 H6509.6 H6510.1 HC1.2 HC3.2 HC5.2 HC6.2 HC7.2 HC8.2 HQ1.2 HQ3.2 HR5.1 HR7.2 HR8.2 HR9.2 HR12.2 HR13.2 HR37.1 HR38.1 HR39.1 HR40.1 HR41.1 HR42.1 HR43.2 HR44.2 HR45.1 HU1.3 HU4.3 J1.1 J1.5 MC1.1 MC2.1 MC3.1 MC4.1 P2.10 P2.13 P2.16 P2.19 P2.22 P2.25 P2.28 P2.31 P2.32 P2.33 P2.34 P2.41 P2.42 P2.43 P2.44 PC3.2 PC4.2 PC6.2 PC7.2 PC8.2 PC9.2 PC10.2 PC11.2 PC12.2 PC13.2 PC14.2 PC15.2 PC16.2 PC17.2 PC18.2 PC19.2 PC20.2 PC21.2 PC23.2 PC24.2 PC25.1 PC26.2 PC27.2 PC28.2 PC29.2 PC30.2 PC31.2 PC32.2 PC33.2 PC34.2 PC35.2 PC36.2 PC37.2 PC38.2 PC39.2 PC40.2 PC42.2 PC43.2 PC44.2 PC45.2 PC46.2 PC47.2 PC50.2 PC51.2 PC52.2 PC53.2 PC54.2 PC57.2 PC59.2 PC61.2 PC63.2 PC64.2 PC65.2 PC67.2 PC68.2 PC69.2 PC71.2 PC72.2 PC73.2 PC74.2 PC75.2 PC76.2 PC77.2 PC78.2 PC83.2 PC84.2 PC85.2 PC87.2 PC88.2 PC90.2 PC92.2 PC94.2 PC95.2 PC96.2 PC97.2 PC98.2 PC99.2 PC100.2 PC101.2 PC102.2 PC103.2 PC104.2 PC105.2 PC106.2 PC107.2 PC108.2 PC109.2 PC110.2 PC111.2 PC113.2 PC114.2 PC115.2 PC117.2 PC119.2 PC121.2 PC122.2 PC124.2 PC125.2 PC128.2 PC129.2 PC131.2 PC132.2 PC133.2 PC136.2 PC138.2 PC139.2 PC141.2 PC142.2 PC143.2 PC144.1 PC147.2 PC149.1 PC150.2 PC151.2 PC152.2 PC153.2 PC155.2 PC156.2 PC157.2 PC158.2 PC159.2 PC160.2 PC161.2 PC163.2 PC164.2 PC165.2 PC166.2 PC167.2 PC169.2 PC170.2 PC171.2 PC172.2 PC174.2 PC175.2 PC176.2 PC177.2 PC182.2 PC184.2 PC186.2 PC187.2 PC188.2 PC189.2 PC190.2 PC194.2 PC195.2 PC196.2 PC197.2 PC198.2 PC199.2 PC200.2 PC201.2 PC202.2 PC203.2 PC213.2 PC218.2 PC219.2 PC220.2 PC221.2 PC222.2 PC223.2 PC224.2 PC225.2 PCE1.2 PCE2.2 PCE3.2 PCE5.2 PCE6.2 PCE7.2 PJP7.2 PQ5.1 PQ5.4 PQ6.1 PQ7.2 PQ8.2 PQ9.1 PQ9.4 PQ10.1 PQ10.4 PQ13.1 PQ13.4 PQ16.4 PQ16.8 PQ18.4 PQ18.8 PQ20.4 PQ20.8 PQ22.4 PQ22.8 PQ25.1 PQ28.2 PQ31.1 PQ32.1 PQ35.1 PR13.2 PR16.2 PR18.2 PR54.2 PR71.2 PR72.2 PR77.2 PR85.1 PR87.2 PR119.2 PR120.2 PR122.2 PR124.1 PR126.2 PR129.2 PR132.2 PR148.2 PR149.1 PR152.1 PR159.2 PR174.2 PR175.2 PR186.2 PR191.2 PR207.2 PR212.2 PR235.2 PR241.2 PU3.14 PU3.21 PU3.22 PU3.23 PU3.24 PU3.25 PU4.19 PU4.29 PU4.33 PU4.34 PU4.35 PU4.36 PU4.37 PU5.3 PU5.9 PU5.10 PU5.11 PU5.12 PU5.13 PU5.14 PU5.15 PU5.16 PU5.17 PU5.18 PU6.21 PU6.22 PU6.23 PU7.1 PU7.3 PU7.11 PU7.14 PU7.21 PU7.22 PU7.23 PU7.24 PU7.25 PU8.2 PU8.14 PU9.2 Q5.1 Q5.4 Q7.1 Q7.4 Q7.5 Q8.2 Q9.2 Q10.2 Q11.2 Q12.2 Q13.2 Q14.2 Q19.2 Q22.2 Q23.2 Q25.2 Q26.2 Q27.1 Q27.4 Q28.2 Q29.1 Q29.4 Q30.1 Q30.4 Q31.1 Q31.4 Q32.2 Q33.2 Q35.2 Q37.2 Q38.2 Q39.2 Q9200.1 Q9200.4 R30.2 R31.2 R32.2 R33.2 R34.2 R35.2 R36.2 R37.2 R44.1 R45.1 R46.1 R47.1 R60.1 R61.1 R62.1 R63.1 R72.2 R85.2 R86.2 R87.2 R96.2 R97.2 R98.2 R99.2 R103.2 R106.2 R108.2 R127.1 R128.1 R131.1 R132.1 R134.1 R176.2 R189.2 R212.2 R217.2 R222.2 R223.2 R224.2 R225.2 R289.2 R291.2 R304.2 R327.2 R328.2 R329.2 R330.2 R335.2 R336.2 R337.2 R338.2 R342.2 R346.2 R348.2 R371.1 R377.2 R382.2 R383.2 R384.2 R385.2 R388.2 R389.2 R400.2 R401.2 R415.2 R440.2 R455.1 R456.1 R457.1 R9330.1 R60358.1 R60364.2 R60365.2 S1R5.2 SC1.2 SC2.2 SC3.2 SC4.2 SC5.2 SC6.2 SC7.2 SC12.2 SP1.2 SR19.2 SR21.2 SR59.2 SR60.2 SR61.2 SR63.2 SR70.1 SR78.2 SR86.2 SR89.2 SR9209.1 SR9210.1 ST9.1 ST29.1 ST30.1 ST31.1 ST32.1 ST33.1 ST34.1 ST35.1 ST36.1 ST37.1 ST38.1 ST39.1 ST40.1 ST41.1 ST42.1 ST43.1 SW1.4 SW1.5 T32.1 T52.1 U1.A11 U1.A14 U1.A18 U1.A24 U1.A28 U1.A32 U1.A36 U1.A40 U1.A44 U1.A48 U1.A52 U1.A56 U1.AA1 U1.AA58 U1.AB7 U1.AB10 U1.AB20 U1.AB22 U1.AC61 U1.AD3 U1.AD21 U1.AD63 U1.AE5 U1.AE10 U1.AE58 U1.AF11 U1.AF12 U1.AF14 U1.AF15 U1.AF17 U1.AF18 U1.AG1 U1.AG11 U1.AG21 U1.AG23 U1.AG60 U1.AG61 U1.AG62 U1.AG63 U1.AH16 U1.AH17 U1.AH19 U1.AH20 U1.AH22 U1.AH24 U1.AH28 U1.AH30 U1.AH32 U1.AH34 U1.AH36 U1.AH38 U1.AH40 U1.AH42 U1.AH44 U1.AH46 U1.AH49 U1.AH51 U1.AH53 U1.AH55 U1.AH57 U1.AJ13 U1.AJ14 U1.AJ23 U1.AJ25 U1.AJ27 U1.AJ29 U1.AJ35 U1.AJ39 U1.AJ41 U1.AJ43 U1.AJ45 U1.AJ47 U1.AJ50 U1.AJ52 U1.AJ54 U1.AJ56 U1.AJ58 U1.AJ60 U1.AJ63 U1.AK3 U1.AK23 U1.AK52 U1.AL10 U1.AL13 U1.AL17 U1.AL20 U1.AL22 U1.AL23 U1.AL26 U1.AL29 U1.AL31 U1.AL33 U1.AL36 U1.AL39 U1.AL40 U1.AL45 U1.AL46 U1.AL51 U1.AL52 U1.AL54 U1.AL57 U1.AL60 U1.AL61 U1.AM1 U1.AM17 U1.AM23 U1.AM31 U1.AM52 U1.AN7 U1.AN17 U1.AN23 U1.AN31 U1.AN32 U1.AN35 U1.AN36 U1.AN39 U1.AN40 U1.AN42 U1.AN43 U1.AN45 U1.AN46 U1.AN48 U1.AN49 U1.AN51 U1.AN52 U1.AN60 U1.AN63 U1.AP3 U1.AP10 U1.AP17 U1.AP20 U1.AP22 U1.AP23 U1.AP26 U1.AP29 U1.AP31 U1.AP38 U1.AP39 U1.AP48 U1.AP52 U1.AP54 U1.AP57 U1.AR5 U1.AR11 U1.AR15 U1.AR17 U1.AR23 U1.AR31 U1.AR33 U1.AR39 U1.AR43 U1.AR49 U1.AR52 U1.AT13 U1.AT35 U1.AT37 U1.AT40 U1.AT42 U1.AT43 U1.AT46 U1.AT49 U1.AT61 U1.AT62 U1.AT63 U1.AU1 U1.AU16 U1.AU18 U1.AU20 U1.AU22 U1.AU24 U1.AU26 U1.AU28 U1.AU30 U1.AU33 U1.AU51 U1.AU53 U1.AU55 U1.AU57 U1.AU59 U1.AV8 U1.AV14 U1.AV16 U1.AV20 U1.AV24 U1.AV28 U1.AV33 U1.AV34 U1.AV36 U1.AV39 U1.AV41 U1.AV43 U1.AV46 U1.AV49 U1.AV51 U1.AV55 U1.AV59 U1.AW4 U1.AW16 U1.AW24 U1.AW33 U1.AW35 U1.AW37 U1.AW40 U1.AW42 U1.AW44 U1.AW47 U1.AW50 U1.AW51 U1.AW59 U1.AW60 U1.AY4 U1.AY6 U1.AY11 U1.AY16 U1.AY18 U1.AY22 U1.AY24 U1.AY26 U1.AY30 U1.AY33 U1.AY51 U1.AY53 U1.AY57 U1.AY59 U1.B4 U1.B20 U1.B24 U1.B26 U1.B28 U1.B32 U1.B36 U1.B40 U1.B44 U1.B48 U1.B52 U1.B56 U1.B60 U1.C11 U1.C14 U1.C18 U1.C20 U1.C25 U1.C27 U1.C38 U1.C39 U1.C57 U1.D2 U1.D5 U1.D8 U1.D12 U1.D14 U1.D18 U1.D21 U1.D23 U1.D25 U1.D26 U1.D27 U1.D29 U1.D30 U1.D31 U1.D33 U1.D34 U1.D35 U1.D37 U1.D38 U1.D39 U1.D41 U1.D42 U1.D43 U1.D45 U1.D46 U1.D47 U1.D49 U1.D50 U1.D51 U1.D53 U1.D54 U1.D55 U1.D57 U1.D59 U1.D62 U1.D63 U1.E11 U1.E17 U1.F20 U1.F26 U1.F30 U1.F34 U1.F38 U1.F42 U1.F46 U1.F50 U1.F54 U1.F58 U1.F61 U1.G3 U1.G5 U1.G6 U1.G8 U1.G18 U1.G22 U1.H13 U1.H17 U1.H57 U1.J10 U1.J22 U1.J59 U1.J63 U1.K1 U1.K12 U1.L7 U1.L13 U1.L15 U1.L17 U1.L18 U1.L20 U1.L58 U1.L61 U1.M22 U1.N3 U1.N10 U1.N21 U1.P22 U1.P59 U1.P62 U1.P63 U1.R8 U1.R10 U1.R22 U1.T1 U1.T58 U1.U9 U1.U20 U1.U22 U1.U61 U1.V3 U1.V7 U1.V10 U1.V23 U1.V58 U1.W20 U1.W22 U1.Y10 U1.Y59 U1.Y63 U2.A9 U2.B1 U2.B3 U2.B9 U2.D1 U2.D3 U2.D8 U2.E1 U2.E2 U2.E7 U2.E8 U2.F9 U2.G1 U2.G8 U2.G9 U2.J2 U2.J8 U2.M1 U2.M9 U2.P1 U2.P9 U2.T1 U2.T9 U3.A9 U3.B1 U3.B3 U3.B9 U3.D1 U3.D3 U3.D8 U3.E1 U3.E2 U3.E7 U3.E8 U3.F9 U3.G1 U3.G8 U3.G9 U3.J2 U3.J8 U3.M1 U3.M9 U3.P1 U3.P9 U3.T1 U3.T9 U4.A9 U4.B1 U4.B3 U4.B9 U4.D1 U4.D3 U4.D8 U4.E1 U4.E2 U4.E7 U4.E8 U4.F9 U4.G1 U4.G8 U4.G9 U4.J2 U4.J8 U4.M1 U4.M9 U4.P1 U4.P9 U4.T1 U4.T9 U5.A9 U5.B1 U5.B3 U5.B9 U5.D1 U5.D3 U5.D8 U5.E1 U5.E2 U5.E7 U5.E8 U5.F9 U5.G1 U5.G8 U5.G9 U5.J2 U5.J8 U5.M1 U5.M9 U5.P1 U5.P9 U5.T1 U5.T9 U6.2 U6.5 U6.62 U6.65 U9.1 U9.2 U9.3 U9.4 U9.8 U9.9 U9.11 U9.18 U9.25 U10.1 U10.27 U10.49 U10.91 U10.113 U10.122 U11.4 U12.5 U13.6 U13.10 U13.18 U13.21 U13.25 U14.6 U14.10 U14.18 U14.21 U14.25 U15.1 U15.5 U16.5 U16.10 U16.12 U16.13 U16.15 U16.16 U17.5 U17.10 U17.12 U17.13 U17.15 U17.16 U19.5 U19.10 U19.12 U19.13 U19.16 U20.5 U20.24 U20.34 U20.35 U21.3 U21.13 U21.21 U21.22 U21.23 U21.24 U21.25 U22.1 U23.1 U24.1 U25.1 UA3.8 UA3.9 UA3.10 UA3.11 UA3.12 UA3.13 V1C21.2 VCB1.2 VCB2.2 VCB3.2 VCB4.2 VCB5.2 VU1.1 VU1.3 VU2.1 VU2.3 VU3.3 VU4.3 VU5.3 X1.2 X1.3 X2.2 X2.3 XDP1.1 XDP1.2 XDP1.7 XDP1.8 XDP1.13 XDP1.14 XDP1.19 XDP1.20 XDP1.25 XDP1.26 XDP1.31 XDP1.32 XDP1.37 XDP1.38 XDP1.49 XDP1.50 XDP1.59
VCC_SENSE: PR130.1 U1.E63
VCCSDIO_R: PC39.1 PR46.2 U1.T9 U1.U8
VDD_EN: R301.1 U6.14 VU5.2
VDDEN: R297.1 R300.2 R301.2 R302.1 R304.1 VU5.4
VSS_SENSE: PR131.1 U1.E62
+1.05A_DCPSUS1: PC30.1 U1.AD8 U1.AD10
+1.05A_DCPSUS2: PC25.2 U1.AH13
+1.05A_VCCUSB3SUS: PC23.1 U1.J13
+1P05V: CKR2.2 GR5.1 GR28.1 GR29.1 GR30.1 GR31.1 HR32.1 HR33.1 HR34.1 L2.1 PC19.1 PC20.1 PC21.1 PC28.1 PC29.1 PC36.1 PC37.1 PC40.1 PC164.1 PC165.1 PC166.1 PC167.1 PC168.1 PJP15.1 PJP16.1 PL3.1 PL4.1 PL5.1 PL20.2 PQ1.3 PR35.2 PR40.1 PR41.1 R230.1 R433.1 SR18.1 U1.AE8 U1.AE9 U1.AF9 U1.AF22 U1.AG8 U1.AG16 U1.AG17 U1.H11 U1.H15 U1.J11 U1.J17 U1.R21 U1.T21
+1P5V: PC175.1 PC176.1 PR55.2 PR56.2 PR57.2 PR189.1 PU9.5 R316.1 U1.J15
+1P05V_BOOT1_D: PC162.1 PR178.2
+1P05V_BOOT_D: PR178.1 PU8.10
+1P05V_EDP: C54.1 C55.1 C56.1 C57.1 C58.1 C59.1 C9206.1 C9207.1 L2.2 U6.1 U6.9 U6.32 U6.46 U6.59
+1P05V_EN_A: PC170.1 PR180.2 PR182.2 PU8.13
+1P05V_FB1_A: PC172.1 PJP16.2 PR185.1
+1P05V_FB_A: PR181.2 PR185.2 PR186.1 PU8.12
+1P5V_FB_A: PR189.2 PR191.1 PU9.4
+1P05V_PHASE_D: PC162.2 PL20.1 PR179.2 PU8.8 PU8.9 PU8.15 PU8.16
+1P05V_PWRGD: C430.1 HR46.2 HU4.2 PR184.2 PU8.4 R60468.1
+1P05V_RC_A: PC168.2 PR179.1 PR181.1
+1P05V_VDD_C: PC160.1 PU8.11
+1P05V_VIN: PC161.1 PC163.1 PL19.2 PU8.1
+1P05V_VOUT_A: PC171.1 PJP15.2 PU8.7
+1P35V_DUAL: C2.1 C3.1 C4.1 C5.1 C6.1 C7.1 C10.1 C11.1 C12.1 C13.1 C14.1 C15.1 C16.1 C17.1 C18.1 C19.1 C20.1 C21.1 C30.1 C31.1 C32.1 C33.1 C34.1 C35.1 C36.1 C37.1 C38.1 C39.1 C40.1 C41.1 C1174.1 C1175.1 C1176.1 C1177.1 C1178.1 C1179.1 C1180.1 C1181.1 C1182.1 C1183.1 CE1.1 D3CE2.1 D3CE3.1 D3CE4.1 D3CE5.1 D3CE6.1 D3CE7.1 D3CE8.1 D3CE9.1 D3CE20.1 D3CE21.1 D3CE22.1 D3CE23.1 D3CE24.1 D3CE25.1 D3CE26.1 D3CE27.1 D3CE28.1 DIMM1.75 DIMM1.76 DIMM1.81 DIMM1.82 DIMM1.87 DIMM1.88 DIMM1.93 DIMM1.94 DIMM1.99 DIMM1.100 DIMM1.105 DIMM1.106 DIMM1.111 DIMM1.112 DIMM1.117 DIMM1.118 DIMM1.123 DIMM1.124 HC1.1 HQ2.3 HU1.5 PC150.1 PC156.1 PCE7.1 PJP14.1 PL18.2 PU7.19 R29.2 R38.1 R40.2 R41.2 R56.2 R57.2 R322.1 U1.AH26 U1.AJ31 U1.AJ33 U1.AJ37 U1.AN33 U1.AP43 U1.AR48 U1.AY35 U1.AY40 U1.AY44 U1.AY50 U2.A1 U2.A8 U2.B2 U2.C1 U2.C9 U2.D2 U2.D9 U2.E9 U2.F1 U2.G7 U2.H2 U2.H9 U2.K2 U2.K8 U2.N1 U2.N9 U2.R1 U2.R9 U3.A1 U3.A8 U3.B2 U3.C1 U3.C9 U3.D2 U3.D9 U3.E9 U3.F1 U3.G7 U3.H2 U3.H9 U3.K2 U3.K8 U3.N1 U3.N9 U3.R1 U3.R9 U4.A1 U4.A8 U4.B2 U4.C1 U4.C9 U4.D2 U4.D9 U4.E9 U4.F1 U4.G7 U4.H2 U4.H9 U4.K2 U4.K8 U4.N1 U4.N9 U4.R1 U4.R9 U5.A1 U5.A8 U5.B2 U5.C1 U5.C9 U5.D2 U5.D9 U5.E9 U5.F1 U5.G7 U5.H2 U5.H9 U5.K2 U5.K8 U5.N1 U5.N9 U5.R1 U5.R9
+1P35V_DUAL_BOOT_C: PR160.1 PU7.18
+1P35V_DUAL_BST_C: PC148.2 PR160.2
+1P35V_DUAL_CS_A: PR175.1 PU7.13
+1P35V_DUAL_FB1_A: PC154.2 PR173.1 PR174.1 PU7.6
+1P35V_DUAL_FB_A: PC154.1 PC155.1 PJP14.2 PR173.2 PU7.5
+1P35V_DUAL_HG_D: PR166.1 PU7.17
+1P35V_DUAL_HG_R_D: PC145.1 PQ21.3 PR161.1 PR166.2
+1P35V_DUAL_LG_D: PR169.1 PU7.15
+1P35V_DUAL_LG_R_D: PC152.1 PQ22.3 PR169.2
+1P35V_DUAL_PHASE_D: PC145.2 PC148.1 PL18.1 PQ21.4 PQ21.8 PQ22.1 PQ22.2 PQ22.5 PQ22.6 PQ22.7 PR161.2 PR167.1 PU7.16
+1P35V_DUAL_PWRGD: PR171.2 R60467.1
+1P35V_DUAL_S3_A: PC149.2 PR162.2 PR163.2 PU7.7
+1P35V_DUAL_S5_A: PC151.1 PR168.2 PU7.8
+1P35V_DUAL_SN_C: PC153.1 PR167.2
+1P35V_DUAL_TON_A: PR165.2 PU7.9
+1P35V_DUAL_VIN: PC142.1 PC147.1 PL17.2 PQ21.1 PQ21.2 PQ21.5 PQ21.6 PQ21.7 PR165.1
+3P3V: C77.1 C85.2 C100.1 C101.1 C162.1 C163.1 C164.1 C165.1 C171.1 C172.1 C173.1 C190.1 C191.1 C192.1 C193.1 C194.1 C198.1 C199.1 C9220.1 CA10.1 CA12.1 CA13.1 CB1.1 CB2.1 CB3.1 CB4.1 CON5.1 CON5.3 CON10.18 CON10.19 CON10.20 CON11.15 D3C5.1 D3C8.1 DIMM1.199 DIMM1.201 GC3.1 GC4.1 GR6.1 GU1.14 GU2.5 HC7.1 HR11.1 HR46.1 HR48.1 HU4.5 L3.1 L4.1 PC33.1 PC174.1 PC188.1 PQ27.2 PR7.1 PR8.1 PR45.2 PR46.1 PR53.1 PR97.1 PR107.1 PR110.1 PR117.1 PR182.1 PR184.1 PR227.2 PR228.1 PR233.1 PR243.1 PU9.1 Q20.1 R71.1 R79.2 R80.1 R81.1 R82.2 R83.2 R84.2 R92.1 R93.1 R94.1 R95.2 R124.2 R125.2 R129.1 R130.1 R133.2 R135.1 R136.1 R137.1 R138.1 R145.1 R146.1 R148.2 R164.1 R173.1 R197.1 R198.1 R226.1 R227.1 R228.1 R233.1 R239.1 R243.1 R251.1 R252.1 R253.1 R254.1 R255.1 R256.1 R278.1 R282.1 R284.2 R300.1 R313.1 R350.1 R354.1 R355.1 R369.1 R370.1 R376.1 R378.1 R379.1 R380.1 R381.1 R386.1 R387.1 R414.1 R416.1 R425.1 R426.1 R427.1 R431.2 R9203.2 R60359.1 R60362.1 R60370.1 R60371.1 R60471.1 RN4.1 RN4.3 RN4.5 RN4.7 S1R4.1 SR3.1 SR8.2 SR13.1 SR14.1 SR16.1 SR27.1 SR29.1 SR50.1 SR51.1 SR52.1 SR62.1 SR71.2 SR72.2 SR77.1 SR87.1 SR88.1 SR90.1 SR9208.1 U1.K14 U1.K16 U9.10 U9.19 U9.24 U10.11 U12.1 U16.1 U16.7 U16.8 U16.14 U17.1 U17.14 U19.1 U19.7 U19.8 U19.14 U19.15 U20.1 U20.4 U20.7 U20.16 U20.23 U20.33 U20.36 U21.6 U21.16 UA3.1 UA3.4 UA3.5 UA3.15 UA3.16 VCB1.1 VCB2.1 VCB3.1 VCB4.1 VCB5.1 VR2.2 VU1.5 VU2.5 VU3.5 VU4.5 VU5.5
+3P3V_DUAL: MC1.2 MC2.2 MC3.2 MC4.2 PC202.1 PQ33.2 PR172.1 R273.1 R319.1 R323.1 R324.1 R325.1 R326.1 R331.1 R332.1 R333.1 R334.1 R353.2 U13.1 U13.13 U14.1 U14.13
+3P3V_DUAL_F: C111.1 C112.1 C113.1 CN1.5 F1.2
+3P3V_DUAL_G_B: PC203.1 PQ33.1 PR223.2
+3P3V_DUAL_P: F1.1 R273.2 R274.2
+3P3V_EDP: C60.1 C9209.1 C9210.1 C9211.1 C9212.1 C9213.1 C9214.1 C9215.1 L3.2 U6.8 U6.13 U6.25 U6.33 U6.39 U6.53 U6.63
+3P3V_G_B: PC189.1 PQ27.1 PR198.2
+3P3V_HK: CON9.6 R350.2 R351.1 R352.1 R353.1
+3P3V_MINI1: C148.1 C149.1 C150.2 CONWIFI.2 CONWIFI.4 CONWIFI.72 CONWIFI.74 R305.1 R306.1 R312.2 R450.1 SC12.1
+3P3V_MSATA: C125.1 C126.1 C127.2 CONSATA.2 CONSATA.4 CONSATA.70 CONSATA.72 CONSATA.74 R282.2 SC7.1
+3P3V_SATA: C94.1 C95.1 C96.1 CON3.P1 CON3.P2 CON3.P3 R233.2 R234.1
+3P3V_SPI: C53.1 F3CB4.1 F3J1.2 F3R2.1 F3R3.1 F3R14.1 F3U1.8 PR227.1 PR229.1
+3P3VA: PC119.1 PR155.1 PU6.3
+3P3VSB: CR2.1 CR3.1 CR4.1 CR7.1 CR9.1 GR4.1 GR32.1 GR33.1 GR34.1 HR10.1 PC223.1 PQ36.2 PR20.1 PR33.1 PR37.1 PR42.1 PR229.2 PR242.1 Q24.2 R88.1 R109.1 R119.1 R240.1 R405.1 R406.2 R407.2 RN1.1 RN1.3 RN3.1 RN3.3 RN8.2 RN8.4 SR1.1 SR4.1 SR28.1 SR35.1 SR36.1 SR79.1 SR80.1 SR81.1 SR82.1
+3P3VSB_G1_B: PC225.1 PQ36.1 PR238.2
+3P3VSB_G_B: PQ35.4 PR235.1 PR238.1
+A/D_DOCK_IN: PD1.1 PD1.2 PD1.3 PD1.4 PL7.2 PL8.2 PR63.1 PR64.1 PR65.1 PR66.1 PR69.1
+A/D_DOCK_IN_B: C151.1 C152.1 D17.2 J1.2 J1.4 PL7.1 PL8.1
+AC_BAT_IN: PC56.1 PQ11.1 PQ11.2 PQ11.3 PQ12.4 PQ12.8 PR76.1
+AC_BAT_SYS: C132.1 C133.1 PC63.1 PC111.1 PC133.1 PC143.1 PC169.1 PC185.1 PC198.1 PF1.1 PJP3.2 PL10.2 PL13.1 PL15.1 PL17.1 PL19.1 PQ14.1 PQ14.2 PQ14.5 PQ14.6 PQ14.7 PQ15.1 PQ15.2 PQ15.5 PQ15.6 PQ15.7 PQ25.3 PQ26.2 PR50.1 PR74.2 PR196.1 PR239.1 R275.1 T46.1 T47.1 T48.1 T49.1 T50.1
+AC_SN_C: PC48.1 PR59.2 PR60.2 PR61.2 PR62.2
+AC_SN_C1: PC49.1 PR63.2 PR64.2 PR65.2 PR66.2
+ADAPTER_IN: C154.1 C155.1 D19.2 PC44.1 PC45.1 PD2.1 PD2.2 PD2.3 PD2.4 PR58.1 PR59.1 PR60.1 PR61.1 PR62.1 PR70.1 U15.2 U15.4
+DUAL_POWER_G_B: PQ32.4 PR206.1 PR212.1 PR223.1
+EXT_DC_IN: PC46.1 PC55.1 PD1.5 PD2.5 PD3.2 PD8.3 PQ11.5 PR73.1 PR79.1
+PCH_VCCDSW: PR43.2 U1.AG19 U1.AG20
+PCH_VCCDSW_R: PC26.1 PR43.1
+RTC_BAT: D1.2 R69.2
+RTCBAT: CON1.2 R69.1 T9208.1
+V_VREF_CA_DIMM: C1188.1 C1189.1 C1190.1 C1191.1 R41.1 R43.1 R45.2 U2.M8 U3.M8 U4.M8 U5.M8
+V_VREF_DQ_DIMM0: C1184.1 C1185.1 C1186.1 C1187.1 R40.1 R42.2 R44.2 U2.H1 U3.H1 U4.H1 U5.H1
+VCORE: PC95.1 PC96.1 PC97.1 PC98.1 PC99.1 PC100.1 PC101.1 PC102.1 PC103.1 PC104.1 PC105.1 PC106.1 PC107.1 PC108.1 PC109.1 PC110.1 PC221.1 PC222.1 PJP6.2 PJP10.2 PL12.2 U1.AB57 U1.AD57 U1.AG57 U1.C24 U1.C28 U1.C32 U1.C36 U1.C40 U1.C44 U1.C48 U1.C52 U1.C56 U1.E23 U1.E25 U1.E27 U1.E29 U1.E31 U1.E33 U1.E35 U1.E37 U1.E39 U1.E41 U1.E43 U1.E45 U1.E47 U1.E49 U1.E51 U1.E53 U1.E55 U1.E57 U1.F24 U1.F28 U1.F32 U1.F36 U1.F40 U1.F44 U1.F48 U1.F52 U1.F56 U1.F59 U1.G23 U1.G25 U1.G27 U1.G29 U1.G31 U1.G33 U1.G35 U1.G37 U1.G39 U1.G41 U1.G43 U1.G45 U1.G47 U1.G49 U1.G51 U1.G53 U1.G55 U1.G57 U1.H23 U1.J23 U1.K23 U1.K57 U1.L22 U1.M23 U1.M57 U1.P57 U1.U57 U1.W57
+VCORE_ALERT#_A: PR98.2 PR105.1 PU4.32
+VCORE_BST1_L1_RC_D: PC91.1 PR136.2
+VCORE_BST1_R1_RC_D: PR136.1 PU5.6
+VCORE_BST1_RC_D: PC91.2 PU5.7
+VCORE_COMP_A: PC81.1 PC82.1 PR114.1 PR115.1 PU4.26
+VCORE_CSN1: PC79.1 PC80.1 PJP10.1 PR113.2 PRT4.2 PU4.18
+VCORE_CSP1: PJP9.1 PR111.2
+VCORE_CSP1_A: PC79.2 PC80.2 PR111.1 PR112.1 PR113.1 PU4.17
+VCORE_CSP1_NTC_A: PR112.2 PRT4.1
+VCORE_CSP2_A: PR117.2 PU4.20
+VCORE_DROOP_A: PC81.2 PR114.2 PR116.2 PU4.25
+VCORE_EN_A: PC78.1 PR102.2 PR107.2 PR217.2 PU4.8
+VCORE_F-IMAX_A: PR123.2 PR124.2 PU4.10
+VCORE_FB+_A: PJP6.1 PR128.1
+VCORE_FB-_A: PJP7.1 PR133.1
+VCORE_GFB_A: PR131.2 PR133.2 PU4.23
+VCORE_IMON1_A: PR127.2 PR224.1
